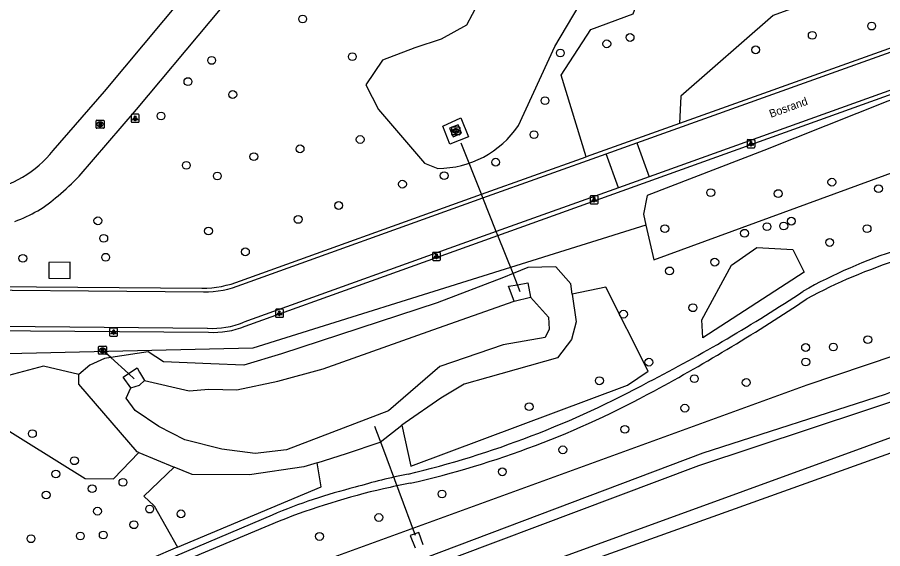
# Model space of a CAD drawing. Extents: x 156664 to 157568, y 383571 to 384421.
# Drawn here: x 156973.2 to 157081.3, y 383715.3 to 383781.8 of the extents above; entities that cross this region are included whole.
import ezdxf

# ---------------------------------------------------------------- set-up
doc = ezdxf.new("R2010")
doc.units = 0
for name, color, linetype in [('IMGEO_Boom', 7, 'Continuous'), ('IMGEO_Duiker', 7, 'Continuous'), ('IMGEO_Fietspad_gesloten', 7, 'Continuous'), ('IMGEO_Groenvoorziening', 7, 'Continuous'), ('IMGEO_Kolk', 7, 'Continuous'), ('IMGEO_Lage_trafo', 7, 'Continuous'), ('IMGEO_Lichtpunt', 7, 'Continuous'), ('IMGEO_Loofbos', 7, 'Continuous'), ('IMGEO_Meer_plas_ven_vijver', 7, 'Continuous'), ('IMGEO_Muur', 7, 'Continuous'), ('IMGEO_Openbare_ruimte_label', 7, 'Continuous'), ('IMGEO_Rijbaan_lokaal_halfverhard', 7, 'Continuous'), ('IMGEO_Rijbaan_lokaal_open', 7, 'Continuous'), ('IMGEO_Rioolput', 7, 'Continuous'), ('IMGEO_Terreindeel_open', 7, 'Continuous'), ('IMGEO_Voetpad_onverhard', 7, 'Continuous'), ('IMGEO_Waterloop', 7, 'Continuous')]:
    doc.layers.add(name, color=color, linetype=linetype)

msp = doc.modelspace()

# ---------------------------------------------------------------- linework, layer by layer
at = {"layer": 'IMGEO_Boom'}
for centre in [(157008.85, 383781.56), (157079.93, 383780.67), (157072.51, 383779.52), (157046.84, 383778.45), (157049.75, 383779.25), (157065.44, 383777.7), (156997.48, 383776.38), (157015.05, 383776.84), (157041.04, 383777.3), (156994.51, 383773.73), (157000.11, 383772.11), (157039.12, 383771.34), (156991.15, 383769.43), (157037.74, 383767.1), (157016.03, 383766.49), (157008.52, 383765.32), (157002.75, 383764.35), (157032.95, 383763.65), (156994.31, 383763.26), (156998.18, 383761.93), (157026.52, 383761.97), (157074.96, 383761.16), (157021.31, 383760.91), (157080.79, 383760.34), (157059.83, 383759.85), (157068.26, 383759.73), (157013.34, 383758.24), (156983.26, 383756.33), (157008.28, 383756.5), (157069.9, 383756.28), (156997.08, 383755.05), (157054.1, 383755.35), (157064.05, 383754.77), (157066.85, 383755.59), (157068.95, 383755.67), (157079.36, 383755.35), (156983.99, 383754.14), (157074.68, 383753.62), (156973.89, 383751.64), (156984.23, 383751.77), (157001.69, 383752.45), (157060.33, 383751.16), (157054.68, 383750.06), (157057.6, 383745.46), (157048.93, 383744.65), (157079.45, 383741.47), (157071.68, 383740.49), (157075.14, 383740.55), (157052.1, 383738.65), (157071.7, 383738.67), (157045.92, 383736.33), (157057.78, 383736.59), (157064.26, 383736.11), (157037.15, 383733.09), (157056.59, 383732.91), (157049.1, 383730.26), (156975.08, 383729.71), (157041.35, 383727.7), (156980.33, 383726.33), (156978.01, 383724.68), (157033.79, 383724.95), (156986.39, 383723.64), (156982.54, 383722.84), (156976.8, 383722.05), (157026.26, 383722.18), (156989.73, 383720.29), (156983.21, 383720.02), (156993.64, 383719.69), (157018.36, 383719.24), (156987.76, 383718.33), (156981.07, 383716.93), (156983.93, 383717.05), (157010.95, 383716.87), (156974.91, 383716.58)]:
    msp.add_circle(centre, 0.489, dxfattribs=at)
at = {"layer": 'IMGEO_Duiker'}
for points in [[(157036.03, 383747.46), (157035.68, 383748.34), (157035.13, 383749.73), (157033.23, 383754.49), (157033.04, 383754.97), (157031.36, 383759.18), (157031.18, 383759.64), (157028.63, 383766.02)], [(156987.81, 383736.56), (156987.07, 383737.23), (156984.86, 383739.23), (156983.85, 383740.14)], [(157017.82, 383730.66), (157018.8, 383728.04), (157022.91, 383717.02)]]:
    msp.add_lwpolyline(points, dxfattribs=at)
at = {"layer": 'IMGEO_Fietspad_gesloten'}
msp.add_lwpolyline([(156835.12, 383639.07), (156845.49, 383642.47), (156918.07, 383668.49), (156979.95, 383690.48), (157000, 383697.71), (157004.59, 383699.36), (157043.51, 383713.39), (157106.61, 383736.03), (157124.32, 383742.33), (157131.66, 383745.02), (157135.74, 383746.91), (157137.6, 383747.87), (157148.48, 383753.68), (157148.48, 383753.68)], dxfattribs=at)
at = {"layer": 'IMGEO_Groenvoorziening'}
for points in [[(157107.82, 383779.35), (157081.94, 383771.28), (157066.47, 383765.12), (157051.89, 383759.47), (157051.41, 383757.17), (157051.73, 383755.8)], [(156818.26, 383643.4), (156825.36, 383646.15), (157071.88, 383735.81), (157097.58, 383744.47), (157105.66, 383748.02), (157115.13, 383751.65), (157124.63, 383755.12), (157127.94, 383756.46), (157131.64, 383758.9), (157143.74, 383766.75), (157148.73, 383769.94)], [(157154.27, 383759.36), (157142.79, 383754.17), (157133.56, 383749.42), (157126.9, 383746.55), (157115.73, 383742.47), (157107.79, 383738.98), (157094.28, 383733.56), (156957.48, 383683.79), (156832.31, 383639.6), (156822.36, 383636.71), (156820.4, 383636.53)], [(157042.52, 383747.16), (157043.02, 383743.68), (157042.42, 383741.47), (157040.7, 383739.19), (157031.96, 383736.75), (157029.03, 383735.92), (157026.09, 383734.14), (157021.65, 383731.09), (157021.25, 383730.78)], [(156988.39, 383727.36), (156988.18, 383727.45), (156980.87, 383735.89), (156980.89, 383737.11)], [(157010.64, 383726.09), (157009, 383725.59), (157002.19, 383724.56), (156995.03, 383724.6), (156992.8, 383725.53)]]:
    msp.add_lwpolyline(points, dxfattribs=at)
at = {"layer": 'IMGEO_Kolk'}
for p, q in [((157027.47, 383767.13), (157027.47, 383767.98)), ((157027.54, 383768.06), (157028.4, 383768.06)), ((157028.4, 383767.06), (157027.54, 383767.06)), ((157027.98, 383767.28), (157027.95, 383767.28)), ((157027.96, 383767.84), (157027.98, 383767.84)), ((157028.47, 383767.98), (157028.47, 383767.13))]:
    msp.add_line(p, q, dxfattribs=at)
for points in [[(157027.47, 383767.13), (157027.47, 383767.98)], [(157027.54, 383768.06), (157028.4, 383768.06)], [(157028.4, 383767.06), (157027.54, 383767.06)], [(157027.79, 383767.76), (157027.91, 383767.76), (157027.91, 383767.61), (157028.04, 383767.76), (157028.21, 383767.76), (157028.06, 383767.61), (157028.21, 383767.36), (157028.06, 383767.36), (157027.98, 383767.52), (157027.91, 383767.46), (157027.91, 383767.36), (157027.79, 383767.36), (157027.79, 383767.76)], [(157028.47, 383767.98), (157028.47, 383767.13)]]:
    msp.add_lwpolyline(points, dxfattribs=at)
for centre, start, end in [((157027.54, 383767.98), 91.552, 178.448), ((157027.54, 383767.98), 91.552, 178.448), ((157027.54, 383767.13), 181.552, 268.448), ((157027.54, 383767.13), 181.552, 268.448), ((157028.39, 383767.98), 1.552, 88.448), ((157028.39, 383767.98), 1.552, 88.448), ((157028.39, 383767.13), 271.552, 358.448), ((157028.39, 383767.13), 271.552, 358.448)]:
    msp.add_arc(centre, 0.0765, start, end, dxfattribs=at)
for centre, major_axis, ratio, start_param, end_param in [((157027.96, 383767.56), (-0.387, 0.002), 0.722429, 4.712389, 7.853982), ((157027.98, 383767.56), (-0.39, 0.002), 0.717154, 1.570796, 4.712389)]:
    msp.add_ellipse(centre, major_axis=major_axis, ratio=ratio, start_param=start_param, end_param=end_param, dxfattribs=at)
at = {"layer": 'IMGEO_Lage_trafo'}
msp.add_lwpolyline([(156979.8, 383751.14), (156977.14, 383751.13), (156977.14, 383749.16), (156979.8, 383749.12), (156979.8, 383751.14)], dxfattribs=at)
at = {"layer": 'IMGEO_Lichtpunt'}
for p, q in [((156987.42, 383769.55), (156987.42, 383768.74)), ((156987.42, 383769.55), (156987.42, 383768.74)), ((156988.32, 383769.64), (156987.51, 383769.64)), ((156988.32, 383769.64), (156987.51, 383769.64)), ((156988.41, 383768.74), (156988.41, 383769.55)), ((156988.41, 383768.74), (156988.41, 383769.55)), ((156987.51, 383768.65), (156988.32, 383768.65)), ((156987.51, 383768.65), (156988.32, 383768.65)), ((157064.36, 383766.38), (157064.36, 383765.57)), ((157064.36, 383766.38), (157064.36, 383765.57)), ((157065.26, 383766.47), (157064.46, 383766.47)), ((157065.26, 383766.47), (157064.46, 383766.47)), ((157065.36, 383765.57), (157065.36, 383766.38)), ((157065.36, 383765.57), (157065.36, 383766.38)), ((157064.46, 383765.47), (157065.26, 383765.47)), ((157064.46, 383765.47), (157065.26, 383765.47)), ((157045.66, 383759.45), (157044.85, 383759.45)), ((157045.66, 383759.45), (157044.85, 383759.45)), ((157044.76, 383759.35), (157044.76, 383758.54)), ((157044.76, 383759.35), (157044.76, 383758.54)), ((157044.85, 383758.45), (157045.66, 383758.45)), ((157044.85, 383758.45), (157045.66, 383758.45)), ((157045.75, 383758.54), (157045.75, 383759.35)), ((157045.75, 383758.54), (157045.75, 383759.35)), ((157025.06, 383752.28), (157025.06, 383751.48)), ((157025.06, 383752.28), (157025.06, 383751.48)), ((157025.96, 383752.38), (157025.16, 383752.38)), ((157025.96, 383752.38), (157025.16, 383752.38)), ((157026.06, 383751.48), (157026.06, 383752.28)), ((157026.06, 383751.48), (157026.06, 383752.28)), ((157025.16, 383751.38), (157025.96, 383751.38)), ((157025.16, 383751.38), (157025.96, 383751.38)), ((157005.44, 383745.17), (157005.44, 383744.36)), ((157005.44, 383745.17), (157005.44, 383744.36)), ((157006.34, 383745.26), (157005.54, 383745.26)), ((157006.34, 383745.26), (157005.54, 383745.26)), ((157006.44, 383744.36), (157006.44, 383745.17)), ((157006.44, 383744.36), (157006.44, 383745.17)), ((157005.54, 383744.27), (157006.34, 383744.27)), ((157005.54, 383744.27), (157006.34, 383744.27)), ((156984.73, 383742.81), (156984.73, 383742)), ((156984.73, 383742.81), (156984.73, 383742)), ((156985.63, 383742.9), (156984.82, 383742.9)), ((156985.63, 383742.9), (156984.82, 383742.9)), ((156985.73, 383742), (156985.73, 383742.81)), ((156985.73, 383742), (156985.73, 383742.81)), ((156984.82, 383741.91), (156985.63, 383741.91)), ((156984.82, 383741.91), (156985.63, 383741.91))]:
    msp.add_line(p, q, dxfattribs=at)
for points in [[(156987.79, 383769.21), (156987.83, 383769.18), (156987.64, 383768.92), (156987.6, 383768.95), (156987.79, 383769.21)], [(156988, 383769.18), (156988.04, 383769.21), (156988.23, 383768.95), (156988.19, 383768.92), (156988, 383769.18)], [(156987.89, 383769.16), (156987.94, 383769.16), (156987.94, 383768.84), (156987.89, 383768.84), (156987.89, 383769.16)], [(157064.74, 383766.04), (157064.78, 383766.01), (157064.59, 383765.75), (157064.55, 383765.78), (157064.74, 383766.04)], [(157064.84, 383765.99), (157064.89, 383765.99), (157064.89, 383765.67), (157064.84, 383765.67), (157064.84, 383765.99)], [(157064.95, 383766.01), (157064.99, 383766.04), (157065.17, 383765.78), (157065.14, 383765.75), (157064.95, 383766.01)], [(157045.13, 383759.01), (157045.17, 383758.99), (157044.98, 383758.72), (157044.94, 383758.75), (157045.13, 383759.01)], [(157045.23, 383758.97), (157045.28, 383758.97), (157045.28, 383758.64), (157045.23, 383758.64), (157045.23, 383758.97)], [(157045.34, 383758.99), (157045.38, 383759.01), (157045.57, 383758.75), (157045.53, 383758.72), (157045.34, 383758.99)], [(157025.44, 383751.95), (157025.48, 383751.92), (157025.29, 383751.66), (157025.25, 383751.69), (157025.44, 383751.95)], [(157025.54, 383751.9), (157025.59, 383751.9), (157025.59, 383751.58), (157025.54, 383751.58), (157025.54, 383751.9)], [(157025.65, 383751.92), (157025.69, 383751.95), (157025.87, 383751.68), (157025.84, 383751.66), (157025.65, 383751.92)], [(157005.82, 383744.83), (157005.85, 383744.81), (157005.67, 383744.54), (157005.63, 383744.57), (157005.82, 383744.83)], [(157005.92, 383744.79), (157005.97, 383744.79), (157005.97, 383744.46), (157005.92, 383744.46), (157005.92, 383744.79)], [(157006.03, 383744.81), (157006.07, 383744.83), (157006.25, 383744.57), (157006.21, 383744.54), (157006.03, 383744.81)], [(156985.1, 383742.47), (156985.14, 383742.44), (156984.95, 383742.18), (156984.92, 383742.21), (156985.1, 383742.47)], [(156985.2, 383742.42), (156985.25, 383742.42), (156985.25, 383742.1), (156985.2, 383742.1), (156985.2, 383742.42)], [(156985.31, 383742.44), (156985.35, 383742.47), (156985.54, 383742.21), (156985.5, 383742.18), (156985.31, 383742.44)]]:
    msp.add_lwpolyline(points, dxfattribs=at)
for centre in [(156987.92, 383769.35), (157064.86, 383766.17), (157045.26, 383759.15), (157025.56, 383752.08), (157005.94, 383744.97), (156985.23, 383742.61)]:
    msp.add_circle(centre, 0.0994, dxfattribs=at)
for centre, start, end in [((156987.51, 383769.55), 90, 180), ((156987.51, 383769.55), 90, 180), ((156988.32, 383769.55), 0, 90), ((156988.32, 383769.55), 0, 90), ((156987.51, 383768.74), 180, 270), ((156987.51, 383768.74), 180, 270), ((156988.32, 383768.74), 270, 0), ((156988.32, 383768.74), 270, 360), ((157064.46, 383766.38), 90, 180), ((157064.46, 383766.38), 90, 180), ((157065.26, 383766.38), 0, 90), ((157065.26, 383766.38), 0, 90), ((157064.46, 383765.57), 180, 270), ((157064.46, 383765.57), 180, 270), ((157065.26, 383765.57), 270, 0), ((157065.26, 383765.57), 270, 360), ((157044.85, 383759.35), 90, 180), ((157044.85, 383759.35), 90, 180), ((157045.66, 383759.35), 0, 90), ((157045.66, 383759.35), 0, 90), ((157044.85, 383758.54), 180, 270), ((157044.85, 383758.54), 180, 270), ((157045.66, 383758.54), 270, 0), ((157045.66, 383758.54), 270, 360), ((157025.16, 383752.28), 90, 180), ((157025.16, 383752.28), 90, 180), ((157025.96, 383752.28), 0, 90), ((157025.96, 383752.28), 0, 90), ((157025.16, 383751.48), 180, 270), ((157025.16, 383751.48), 180, 270), ((157025.96, 383751.48), 270, 0), ((157025.96, 383751.48), 270, 360), ((157005.54, 383745.17), 90, 180), ((157005.54, 383745.17), 90, 180), ((157005.54, 383744.36), 180, 270), ((157005.54, 383744.36), 180, 270), ((157006.34, 383745.17), 0, 90), ((157006.34, 383745.17), 0, 90), ((157006.34, 383744.36), 270, 0), ((157006.34, 383744.36), 270, 360), ((156984.82, 383742.81), 90, 180), ((156984.82, 383742.81), 90, 180), ((156985.63, 383742.81), 0, 90), ((156985.63, 383742.81), 0, 90), ((156984.82, 383742), 180, 270), ((156984.82, 383742), 180, 270), ((156985.63, 383742), 270, 0), ((156985.63, 383742), 270, 360)]:
    msp.add_arc(centre, 0.0946, start, end, dxfattribs=at)
at = {"layer": 'IMGEO_Loofbos'}
for points in [[(157044.28, 383764.34), (157041.16, 383774.55), (157044.86, 383780.23), (157050.13, 383782.21), (157052.9, 383789.86), (157057.65, 383792.5), (157067.42, 383803.71), (157075.2, 383811.1), (157078.5, 383816.91), (157083.25, 383825.48), (157079.42, 383827.99), (157075.73, 383832.48), (157070.32, 383836.83), (157065.7, 383839.6), (157058.84, 383842.11), (157053.93, 383851.23)], [(157104.05, 383785.76), (157100.64, 383794.07), (157067.61, 383781.99), (157056.08, 383771.91), (157055.93, 383768.51)], [(157051.73, 383755.8), (157052.72, 383751.45), (157102.46, 383769.64), (157103.23, 383774.69), (157106.93, 383776.49), (157108.25, 383771.85), (157111.44, 383764.52), (157114.54, 383765.38)], [(157051.73, 383755.8), (157034.82, 383750.5), (157002.63, 383740.41), (156953.89, 383739.27), (156797.72, 383682.96)], [(157071.48, 383749.89), (157058.86, 383741.7), (157058.73, 383743.96), (157062.42, 383750.78), (157065.57, 383752.98), (157070.08, 383752.76), (157071.48, 383749.89)], [(157042.52, 383747.16), (157042.33, 383748.43), (157040.48, 383750.57), (157036.99, 383750.47), (157035.13, 383749.73), (157033.92, 383749.25), (157025.65, 383746.09), (157006.18, 383739.69), (157001.49, 383738.27), (156997.38, 383738.45), (156991.45, 383738.71), (156989.53, 383739.93), (156984.86, 383739.23), (156984.1, 383739.12), (156982.25, 383738.29), (156980.89, 383737.11)], [(157021.25, 383730.78), (157022.36, 383725.64), (157049.42, 383735.8), (157052.03, 383737.53), (157046.74, 383748.03), (157042.52, 383747.16)], [(156980.89, 383737.11), (156976.46, 383738.17), (156970.79, 383736.66), (156969.84, 383735.98)], [(156969.84, 383735.98), (156966.48, 383733.58), (156981.67, 383724.11), (156985.22, 383724.07), (156988.39, 383727.36)], [(157010.64, 383726.09), (157014.33, 383727.22), (157018.52, 383728.66), (157021.25, 383730.78)], [(156988.39, 383727.36), (156992.8, 383725.53)], [(156993.19, 383715.51), (157011.16, 383723.08), (157010.64, 383726.09)], [(156992.8, 383725.53), (156989.01, 383721.91), (156990.28, 383720.71), (156993.19, 383715.51)], [(156993.19, 383715.51), (156989.91, 383714.12), (156983.73, 383711.79), (156967.54, 383706.76), (156960.58, 383704.39), (156947.11, 383698.61), (156925.49, 383690.09), (156916.78, 383686.98), (156907.11, 383684.23), (156898.18, 383681.26), (156876.31, 383672.99), (156854.26, 383663.23), (156843.61, 383659.07), (156834.34, 383655.68)]]:
    msp.add_lwpolyline(points, dxfattribs=at)
at = {"layer": 'IMGEO_Meer_plas_ven_vijver'}
for points in [[(157035.79, 383768.25), (157040.33, 383778.1), (157044.19, 383784.6), (157048.79, 383787.72), (157058.8, 383796.03), (157064.69, 383801.72), (157067.16, 383805.91), (157069.85, 383808.66), (157073.49, 383812.61), (157077.77, 383818.86), (157077.4, 383822.84), (157074.95, 383825.42), (157071.68, 383826.1), (157068.88, 383825.73), (157068.65, 383824.95), (157070.29, 383821.34)], [(157030.63, 383786.19), (157030.74, 383783.44), (157029.3, 383780.78), (157026.16, 383779.03), (157022.85, 383777.97), (157018.83, 383776.41), (157016.74, 383773.33), (157018.32, 383770.23), (157024.08, 383763.54), (157025.72, 383762.88)], [(157028.61, 383769.2), (157029.58, 383766.82), (157027.24, 383765.91), (157026.35, 383768.17), (157028.61, 383769.2)]]:
    msp.add_lwpolyline(points, dxfattribs=at)
msp.add_arc((157025.75, 383774.95), 12.07, 269.8891, 326.2914, dxfattribs=at)
at = {"layer": 'IMGEO_Muur'}
msp.add_lwpolyline([(157023.89, 383715.82), (157023.36, 383717.35), (157022.27, 383716.98), (157022.88, 383715.46)], dxfattribs=at)
at = {"layer": 'IMGEO_Rijbaan_lokaal_halfverhard'}
for points in [[(157104.05, 383785.76), (157055.93, 383768.51)], [(157001.66, 383743.15), (157033.23, 383754.49), (157107.19, 383781.07)], [(157055.93, 383768.51), (157044.28, 383764.34)], [(157001.06, 383748.84), (157031.18, 383759.64), (157044.28, 383764.34)], [(156958.18, 383748.22), (156975.59, 383748.08), (156996.26, 383747.92)], [(156958.12, 383742.69), (156997.09, 383742.39)]]:
    msp.add_lwpolyline(points, dxfattribs=at)
for centre, radius, start, end in [((156996.4, 383760.12), 12.21, 269.3376, 292.4219), ((156997.68, 383752.9), 10.53, 266.7844, 292.181)]:
    msp.add_arc(centre, radius, start, end, dxfattribs=at)
at = {"layer": 'IMGEO_Rijbaan_lokaal_open'}
for points in [[(156977.66, 383765.11), (156984.1, 383772.51), (157042.75, 383842.78), (157045.99, 383846.98)], [(156980.92, 383761.92), (156988.1, 383770.25), (157006.48, 383792.28)], [(157050.58, 383766.08), (157105.54, 383785.8)], [(157107.02, 383781.52), (157052.15, 383761.84)], [(157046.77, 383764.71), (157050.58, 383766.08)], [(157050.58, 383766.08), (157052.15, 383761.84)], [(157001.24, 383748.37), (157031.36, 383759.18), (157046.77, 383764.71)], [(157048.31, 383760.46), (157046.77, 383764.71)], [(157052.15, 383761.84), (157048.31, 383760.46)], [(157048.31, 383760.46), (157033.04, 383754.97), (157001.5, 383743.65)], [(156958.14, 383747.76), (156996.45, 383747.45)], [(156996.93, 383742.88), (156958.21, 383743.22)]]:
    msp.add_lwpolyline(points, dxfattribs=at)
for centre, radius, start, end in [((156966.98, 383773.49), 13.57, 279.0659, 321.884), ((156958.01, 383783.91), 31.76, 309.6529, 316.1763), ((156967.72, 383771.09), 15.71, 289.1964, 312.233), ((156996.59, 383759.65), 12.21, 269.3376, 292.4219), ((156997.53, 383753.4), 10.53, 266.7844, 292.181)]:
    msp.add_arc(centre, radius, start, end, dxfattribs=at)
at = {"layer": 'IMGEO_Rioolput'}
for p, q in [((156983.03, 383767.97), (156983.03, 383768.82)), ((156983.11, 383768.9), (156983.96, 383768.9)), ((156983.52, 383768.68), (156983.54, 383768.68)), ((156983.54, 383768.12), (156983.52, 383768.12)), ((156984.03, 383768.82), (156984.03, 383767.97)), ((156983.96, 383767.9), (156983.11, 383767.9)), ((156983.35, 383739.72), (156983.35, 383740.57)), ((156983.42, 383740.65), (156984.27, 383740.65)), ((156983.83, 383740.42), (156983.86, 383740.42)), ((156984.35, 383740.57), (156984.35, 383739.72)), ((156984.27, 383739.64), (156983.42, 383739.64)), ((156983.86, 383739.87), (156983.83, 383739.87))]:
    msp.add_line(p, q, dxfattribs=at)
for points in [[(156983.03, 383767.97), (156983.03, 383768.82)], [(156983.11, 383768.9), (156983.96, 383768.9)], [(156983.62, 383768.59), (156983.37, 383768.6), (156983.37, 383768.2)], [(156983.37, 383768.2), (156983.49, 383768.2), (156983.49, 383768.36), (156983.5, 383768.36)], [(156983.55, 383768.52), (156983.49, 383768.52), (156983.49, 383768.43)], [(156983.49, 383768.43), (156983.54, 383768.43)], [(156983.55, 383768.33), (156983.62, 383768.2), (156983.76, 383768.2), (156983.7, 383768.32)], [(156984.03, 383768.82), (156984.03, 383767.97)], [(156983.96, 383767.9), (156983.11, 383767.9)], [(156983.35, 383739.72), (156983.35, 383740.57)], [(156983.42, 383740.65), (156984.27, 383740.65)], [(156983.94, 383740.34), (156983.68, 383740.34), (156983.68, 383739.94)], [(156983.68, 383739.94), (156983.81, 383739.94), (156983.81, 383740.11), (156983.82, 383740.11)], [(156983.86, 383740.26), (156983.81, 383740.26), (156983.81, 383740.18)], [(156983.81, 383740.18), (156983.86, 383740.18)], [(156983.86, 383740.08), (156983.94, 383739.94), (156984.08, 383739.94), (156984.01, 383740.07)], [(156984.35, 383740.57), (156984.35, 383739.72)], [(156984.27, 383739.64), (156983.42, 383739.64)]]:
    msp.add_lwpolyline(points, dxfattribs=at)
for centre, radius, start, end in [((156983.11, 383768.82), 0.0765, 91.552, 178.448), ((156983.11, 383768.82), 0.0765, 91.552, 178.448), ((156983.5, 383768.31), 0.0533, 26.0293, 88.6989), ((156983.53, 383768.62), 0.19, 274.7715, 282.9687), ((156983.55, 383768.42), 0.0964, 77.0061, 93.1865), ((156983.57, 383768.48), 0.0378, 276.6634, 79.6772), ((156983.62, 383768.49), 0.109, 350.3612, 89.416), ((156983.62, 383768.48), 0.112, 277.5842, 350.9817), ((156983.6, 383768.27), 0.108, 29.5134, 73.7905), ((156983.96, 383768.82), 0.0765, 1.552, 88.448), ((156983.96, 383768.82), 0.0765, 1.552, 88.448), ((156983.11, 383767.97), 0.0765, 181.552, 268.448), ((156983.11, 383767.97), 0.0765, 181.552, 268.448), ((156983.96, 383767.97), 0.0765, 271.552, 358.448), ((156983.96, 383767.97), 0.0765, 271.552, 358.448), ((156983.42, 383740.57), 0.0765, 91.552, 178.448), ((156983.42, 383740.57), 0.0765, 91.552, 178.448), ((156983.82, 383740.05), 0.0533, 26.0293, 88.6989), ((156983.87, 383740.17), 0.0964, 77.0061, 93.1865), ((156983.84, 383740.37), 0.19, 274.7715, 282.9687), ((156983.88, 383740.22), 0.0378, 276.6634, 79.6772), ((156983.93, 383740.23), 0.109, 350.3612, 89.416), ((156983.93, 383740.23), 0.112, 277.5842, 350.9817), ((156983.92, 383740.02), 0.108, 29.5134, 73.7905), ((156984.27, 383740.57), 0.0765, 1.552, 88.448), ((156984.27, 383740.57), 0.0765, 1.552, 88.448), ((156983.42, 383739.72), 0.0765, 181.552, 268.448), ((156983.42, 383739.72), 0.0765, 181.552, 268.448), ((156984.27, 383739.72), 0.0765, 271.552, 358.448), ((156984.27, 383739.72), 0.0765, 271.552, 358.448)]:
    msp.add_arc(centre, radius, start, end, dxfattribs=at)
for centre, major_axis, ratio, start_param, end_param in [((156983.52, 383768.4), (-0.387, 0.002), 0.722429, 4.712389, 7.853982), ((156983.54, 383768.4), (-0.39, 0.002), 0.717154, 1.570796, 4.712389), ((156983.83, 383740.14), (-0.387, 0.002), 0.722429, 4.712389, 7.853982), ((156983.86, 383740.14), (-0.39, 0.002), 0.717154, 1.570796, 4.712389)]:
    msp.add_ellipse(centre, major_axis=major_axis, ratio=ratio, start_param=start_param, end_param=end_param, dxfattribs=at)
at = {"layer": 'IMGEO_Terreindeel_open'}
for points in [[(157028.27, 383768.32), (157027.21, 383767.91), (157027.64, 383766.84), (157028.69, 383767.27), (157028.27, 383768.32)], [(157035.25, 383746.26), (157034.54, 383748.14), (157035.68, 383748.34), (157036.96, 383748.57), (157037.3, 383746.8)], [(156987.39, 383735.45), (156986.4, 383736.79), (156987.07, 383737.23), (156988.15, 383737.96), (156988.47, 383737.4), (156989.09, 383736.35)]]:
    msp.add_lwpolyline(points, dxfattribs=at)
at = {"layer": 'IMGEO_Voetpad_onverhard'}
for points in [[(157005.03, 383719.54), (156983.34, 383710.33), (156937.46, 383693.88), (156907.54, 383683)], [(157005.9, 383718.77), (156983.56, 383709.4), (156937.78, 383692.97), (156913.84, 383684.03), (156907.76, 383681.76)]]:
    msp.add_lwpolyline(points, dxfattribs=at)
for centre, radius, start, end in [((157103.22, 383690.74), 65.11, 96.3722, 119.2946), ((157103.2, 383688.73), 65.8, 96.3205, 118.4786), ((156958.07, 383918.4), 205.03, 297.2863, 303.5467), ((156940.89, 383942.13), 235.35, 298.3887, 303.8056), ((156993.19, 383844.52), 123.29, 283.5185, 298.5195), ((156996.07, 383838.66), 118.09, 282.8288, 298.7043), ((157034.83, 383658.67), 67.21, 100.9981, 106.7878), ((157030.88, 383659.35), 65.51, 103.6492, 113.2438), ((157039.23, 383634.47), 90.65, 102.9193, 111.5708), ((157040.32, 383629.12), 96.1, 100.8151, 102.8424)]:
    msp.add_arc(centre, radius, start, end, dxfattribs=at)
at = {"layer": 'IMGEO_Waterloop'}
for points in [[(157151.24, 383765.15), (157134.53, 383755.88), (157125.61, 383751.99), (157114.52, 383747.76), (157081.61, 383734.6), (157058.85, 383727.28), (157013.96, 383710.31), (156901.06, 383669.84), (156833.19, 383645.04), (156819.46, 383640.51), (156819.84, 383639.25), (156850.23, 383649.57), (156897.55, 383667.14), (156937.77, 383681.3), (156977.08, 383695.66), (157013.16, 383708.73), (157058.33, 383725.73), (157086.26, 383734.97), (157115.55, 383746.16), (157124.7, 383749.59), (157132.7, 383752.79), (157139.78, 383755.88), (157146.43, 383759.19), (157152.69, 383762.39)], [(157037.3, 383746.8), (157039.54, 383744.28), (157039.66, 383742.78), (157039.14, 383741.72), (157033.91, 383740.81), (157025.98, 383738.12), (157019.56, 383732.55), (157006.82, 383727.69), (157002.89, 383727.24), (156998.76, 383727.76), (156994.13, 383728.96), (156990.88, 383730.62), (156987.92, 383732.61), (156986.79, 383734.14), (156987.39, 383735.45)], [(157035.25, 383746.26), (157037.3, 383746.8)], [(156989.09, 383736.35), (156994.67, 383735.07), (156997.14, 383735.29), (157000.64, 383735.21), (157005.74, 383736.28), (157011.39, 383737.82), (157025.12, 383742.7), (157035.25, 383746.26)], [(156987.39, 383735.45), (156988.46, 383735.78), (156989.09, 383736.35)]]:
    msp.add_lwpolyline(points, dxfattribs=at)

# ---------------------------------------------------------------- texts
at = {"layer": 'IMGEO_Openbare_ruimte_label'}
msp.add_text('Bosrand', height=1, rotation=19.8118, dxfattribs=at).set_placement((157067.35, 383769.19))

doc.saveas('drawing.dxf')
